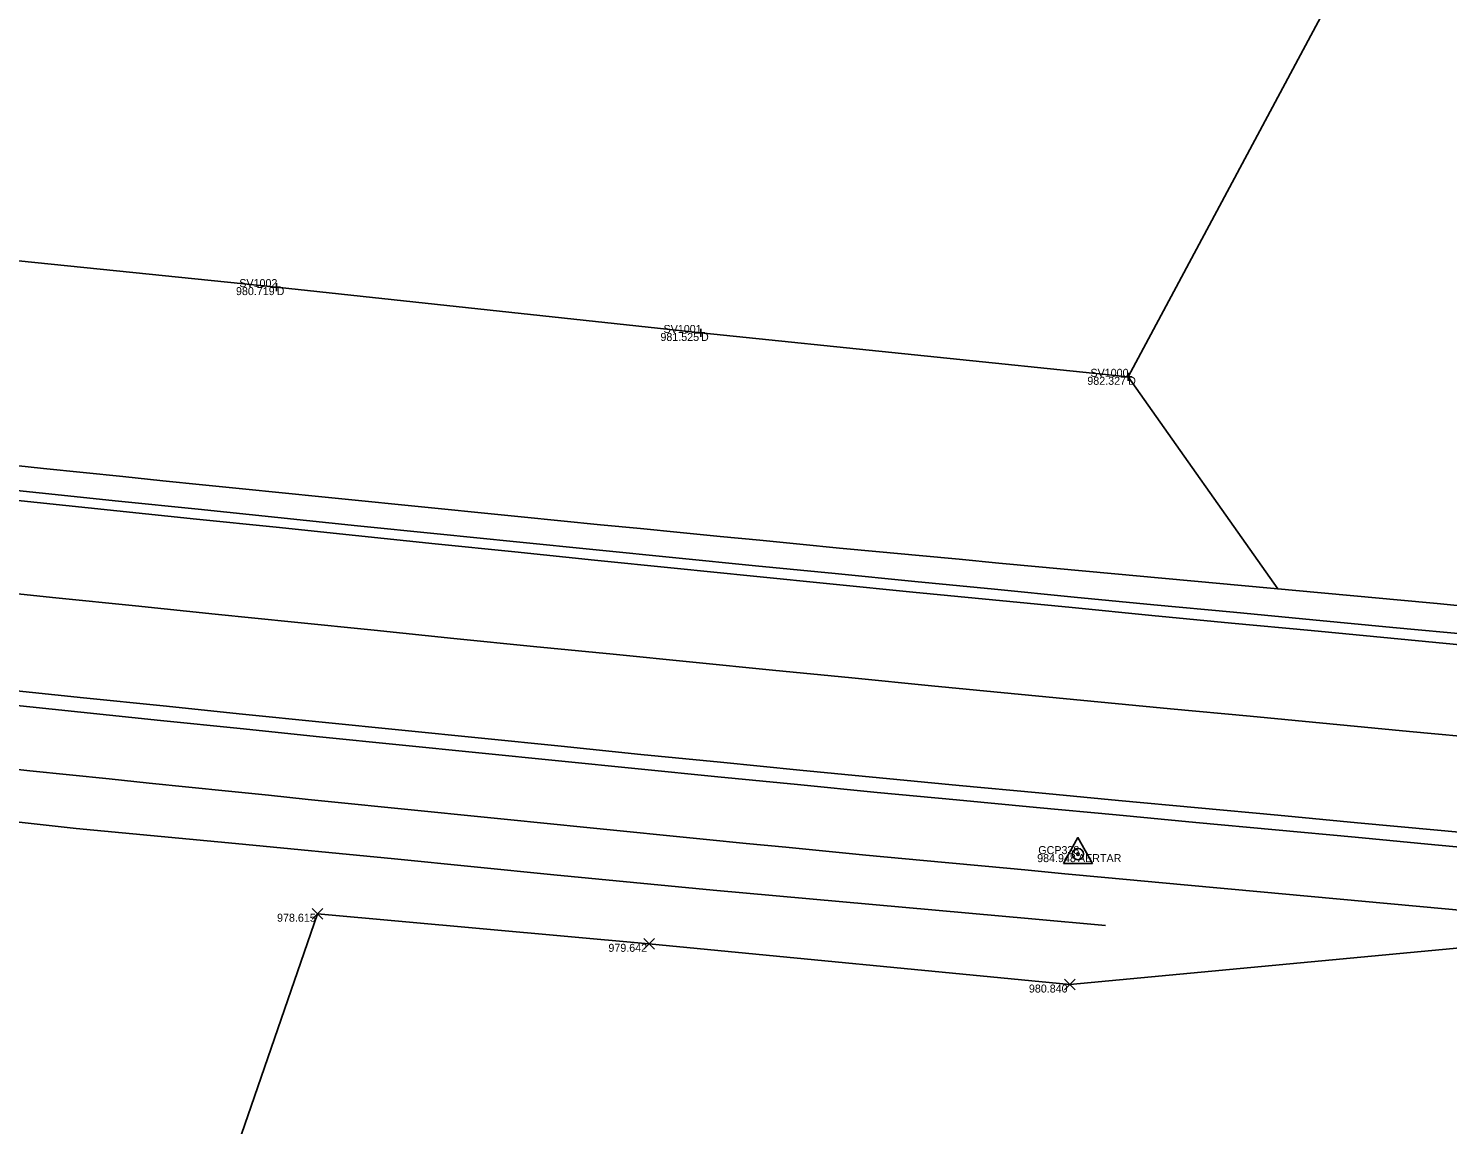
# Model space of a CAD drawing. Extents: x 2065431 to 2068157, y 709104 to 709719.
# Drawn here: x 2067334.4 to 2067511.8, y 709241.9 to 709378.9 of the extents above; entities that cross this region are included whole.
import ezdxf

# ---------------------------------------------------------------- set-up
doc = ezdxf.new("R2010")
doc.units = 0
for name, color, linetype in [('DT_X_Break_Line', 7, 'Continuous'), ('DT_X_Terrain_Boundary', 7, 'Continuous'), ('PM_X_Edge_Line', 7, 'Continuous'), ('PM_X_Lane_Line', 7, 'Continuous'), ('PV_X_EOP', 7, 'Continuous'), ('PV_X_Shoulder_Rumble_Strip', 7, 'Continuous'), ('RS_Raster1', 7, 'Continuous'), ('RW_X_CL_100_Bearings', 7, 'Continuous'), ('RW_X_Fee_WL', 7, 'Continuous'), ('SV_P_Aerial_Targets', 7, 'Continuous'), ('SV_X_Mon_Cells_Found', 7, 'Continuous'), ('SV_X_Text_Elevation', 7, 'Continuous'), ('SV_X_Text_Name', 7, 'Continuous')]:
    doc.layers.add(name, color=color, linetype=linetype)

msp = doc.modelspace()

# ---------------------------------------------------------------- linework, layer by layer
at = {"layer": 'DT_X_Break_Line'}
msp.add_lwpolyline([(2067101.73, 709304.2), (2067121.64, 709302.33), (2067141.54, 709300.39), (2067161.43, 709298.3), (2067181.3, 709296.03), (2067201.15, 709293.56), (2067221.05, 709291.6), (2067240.96, 709289.7), (2067260.87, 709287.74), (2067280.77, 709285.77), (2067300.65, 709283.57), (2067320.49, 709281.09), (2067340.37, 709278.88), (2067360.28, 709276.99), (2067380.18, 709275.07), (2067400.09, 709273.09), (2067419.99, 709271.15), (2067439.91, 709269.35), (2067459.83, 709267.56), (2067469.03, 709266.73)], dxfattribs=at)
at = {"layer": 'DT_X_Terrain_Boundary'}
for points in [[(2067515.45, 709306.5), (2067510.47, 709306.96), (2067505.49, 709307.42), (2067500.51, 709307.88), (2067495.53, 709308.34), (2067490.55, 709308.8), (2067471.85, 709335.31), (2067499.1, 709386.26), (2067504.26, 709386.13), (2067509.24, 709385.64), (2067514.22, 709385.16)], [(2067102.37, 709178.61), (2067140.67, 709165.08), (2067183.02, 709149.8), (2067239.23, 709115.87), (2067261.89, 709104.93), (2067274.06, 709104.86), (2067277.37, 709106.22), (2067284.73, 709107.64), (2067304.22, 709108.67), (2067329.31, 709129.97), (2067346.3, 709160.09), (2067342.01, 709185.45), (2067370.56, 709268.21), (2067411.97, 709264.45), (2067464.57, 709259.36), (2067538.62, 709266.34)]]:
    msp.add_lwpolyline(points, dxfattribs=at)
at = {"layer": 'PM_X_Edge_Line'}
for points in [[(2067325.57, 709320.65), (2067335.52, 709319.61), (2067345.46, 709318.57), (2067355.41, 709317.53), (2067365.36, 709316.5), (2067375.3, 709315.47), (2067385.25, 709314.45), (2067395.2, 709313.43), (2067405.15, 709312.41), (2067415.1, 709311.4), (2067425.04, 709310.4), (2067434.99, 709309.4), (2067444.95, 709308.41), (2067454.9, 709307.44), (2067464.85, 709306.47), (2067474.8, 709305.5), (2067484.76, 709304.54), (2067494.71, 709303.59), (2067504.67, 709302.64), (2067514.62, 709301.7)], [(2067331.35, 709296.24), (2067341.29, 709295.21), (2067351.24, 709294.18), (2067361.19, 709293.16), (2067371.14, 709292.14), (2067381.09, 709291.13), (2067391.04, 709290.13), (2067400.99, 709289.13), (2067410.94, 709288.13), (2067420.89, 709287.14), (2067430.84, 709286.16), (2067440.79, 709285.19), (2067450.75, 709284.25), (2067460.7, 709283.31), (2067470.66, 709282.37), (2067480.62, 709281.44), (2067490.57, 709280.51), (2067500.53, 709279.58), (2067510.49, 709278.66), (2067520.44, 709277.73)]]:
    msp.add_lwpolyline(points, dxfattribs=at)
at = {"layer": 'PM_X_Lane_Line'}
msp.add_lwpolyline([(2067327.9, 709308.73), (2067337.84, 709307.7), (2067347.79, 709306.67), (2067357.74, 709305.65), (2067367.69, 709304.64), (2067377.64, 709303.63), (2067387.59, 709302.62), (2067397.54, 709301.62), (2067407.49, 709300.63), (2067417.44, 709299.64), (2067427.39, 709298.66), (2067437.34, 709297.68), (2067447.29, 709296.71), (2067457.25, 709295.75), (2067467.2, 709294.79), (2067477.15, 709293.83), (2067487.11, 709292.88), (2067497.07, 709291.94), (2067507.02, 709291), (2067516.98, 709290.07)], dxfattribs=at)
at = {"layer": 'PV_X_EOP'}
for points in [[(2067331.31, 709324.38), (2067336.29, 709323.87), (2067341.26, 709323.35), (2067346.23, 709322.84), (2067351.21, 709322.33), (2067356.18, 709321.82), (2067361.16, 709321.32), (2067366.13, 709320.81), (2067371.1, 709320.31), (2067376.08, 709319.81), (2067381.05, 709319.31), (2067386.03, 709318.81), (2067391, 709318.31), (2067395.98, 709317.82), (2067400.96, 709317.32), (2067405.93, 709316.83), (2067410.91, 709316.34), (2067415.88, 709315.85), (2067420.86, 709315.36), (2067425.84, 709314.88), (2067430.81, 709314.4), (2067435.79, 709313.91), (2067440.77, 709313.43), (2067445.74, 709312.96), (2067450.72, 709312.5), (2067455.7, 709312.03), (2067460.68, 709311.57), (2067465.66, 709311.11), (2067470.64, 709310.64), (2067475.61, 709310.18), (2067480.59, 709309.72), (2067485.57, 709309.26), (2067490.55, 709308.8), (2067495.53, 709308.34), (2067500.51, 709307.88), (2067505.49, 709307.42), (2067510.47, 709306.96), (2067515.45, 709306.5)], [(2067329.6, 709286.6), (2067334.58, 709286.08), (2067339.55, 709285.57), (2067344.52, 709285.05), (2067349.5, 709284.54), (2067354.47, 709284.03), (2067359.44, 709283.52), (2067364.42, 709283.01), (2067369.39, 709282.5), (2067374.37, 709281.99), (2067379.34, 709281.49), (2067384.32, 709280.98), (2067389.29, 709280.48), (2067394.27, 709279.98), (2067399.24, 709279.48), (2067404.22, 709278.98), (2067409.19, 709278.49), (2067414.17, 709277.99), (2067419.14, 709277.5), (2067424.12, 709277), (2067429.09, 709276.51), (2067434.07, 709276.02), (2067439.05, 709275.54), (2067444.02, 709275.07), (2067449, 709274.61), (2067453.98, 709274.14), (2067458.96, 709273.68), (2067463.94, 709273.21), (2067468.92, 709272.75), (2067473.89, 709272.29), (2067478.87, 709271.83), (2067483.85, 709271.37), (2067488.83, 709270.9), (2067493.81, 709270.45), (2067498.79, 709269.99), (2067503.77, 709269.53), (2067508.75, 709269.07), (2067513.73, 709268.61)]]:
    msp.add_lwpolyline(points, dxfattribs=at)
at = {"layer": 'PV_X_Shoulder_Rumble_Strip'}
for points in [[(2067325.8, 709321.87), (2067335.75, 709320.82), (2067345.69, 709319.78), (2067355.64, 709318.75), (2067365.59, 709317.72), (2067375.53, 709316.7), (2067385.48, 709315.69), (2067395.43, 709314.68), (2067405.38, 709313.68), (2067415.33, 709312.68), (2067425.28, 709311.69), (2067435.23, 709310.71), (2067445.19, 709309.73), (2067455.14, 709308.76), (2067465.09, 709307.79), (2067475.05, 709306.83), (2067485, 709305.88), (2067494.95, 709304.93), (2067504.91, 709303.98), (2067514.87, 709303.05)], [(2067331.03, 709294.43), (2067340.97, 709293.4), (2067350.92, 709292.37), (2067360.87, 709291.35), (2067370.81, 709290.33), (2067380.76, 709289.32), (2067390.71, 709288.32), (2067400.66, 709287.32), (2067410.61, 709286.32), (2067420.56, 709285.33), (2067430.52, 709284.35), (2067440.47, 709283.38), (2067450.42, 709282.44), (2067460.38, 709281.5), (2067470.34, 709280.56), (2067480.29, 709279.63), (2067490.25, 709278.7), (2067500.21, 709277.77), (2067510.16, 709276.84), (2067520.12, 709275.92)]]:
    msp.add_lwpolyline(points, dxfattribs=at)
at = {"layer": 'RS_Raster1'}
for p, q in [((2067364.94, 709346.52), (2067365.94, 709346.52)), ((2067365.44, 709347.02), (2067365.44, 709346.02)), ((2067365.44, 709346.52), (2067365.44, 709346.52)), ((2067417.97, 709340.79), (2067418.97, 709340.79)), ((2067418.47, 709341.29), (2067418.47, 709340.29)), ((2067418.47, 709340.79), (2067418.47, 709340.79)), ((2067471.35, 709335.31), (2067472.35, 709335.31)), ((2067471.85, 709335.81), (2067471.85, 709334.81)), ((2067471.85, 709335.31), (2067471.85, 709335.31))]:
    msp.add_line(p, q, dxfattribs=at)
at = {"layer": 'RW_X_CL_100_Bearings'}
for p, q in [((2067369.89, 709267.54), (2067371.23, 709268.87)), ((2067369.89, 709268.87), (2067371.23, 709267.54)), ((2067411.31, 709263.79), (2067412.64, 709265.12)), ((2067411.31, 709265.12), (2067412.64, 709263.79)), ((2067463.9, 709258.7), (2067465.23, 709260.03)), ((2067463.9, 709260.03), (2067465.23, 709258.7))]:
    msp.add_line(p, q, dxfattribs=at)
at = {"layer": 'RW_X_Fee_WL'}
msp.add_lwpolyline([(2067471.85, 709335.31), (2067418.47, 709340.79), (2067365.44, 709346.52), (2067311.12, 709352.06), (2067246.93, 709356.31), (2067194.13, 709363.68), (2067159.44, 709368.67)], dxfattribs=at)
at = {"layer": 'SV_P_Aerial_Targets'}
msp.add_lwpolyline([(2067463.78, 709274.5), (2067467.38, 709274.5), (2067465.58, 709277.72)], close=True, dxfattribs=at)
for radius in [0.7, 0.16]:
    msp.add_circle((2067465.58, 709275.66), radius, dxfattribs=at)

# ---------------------------------------------------------------- texts
at = {"layer": 'SV_X_Mon_Cells_Found'}
for s, p in [('SV1002', (2067360.77, 709346.52)), ('SV1001', (2067413.79, 709340.79)), ('SV1000', (2067467.14, 709335.31)), ('GCP338', (2067460.62, 709275.66))]:
    msp.add_text(s, height=1, dxfattribs=at).set_placement(p)
at = {"layer": 'SV_X_Text_Elevation'}
for s, p in [('D', (2067365.44, 709345.52)), ('D', (2067418.47, 709339.79)), ('D', (2067471.85, 709334.31)), ('AERTAR', (2067465.58, 709274.66))]:
    msp.add_text(s, height=1, dxfattribs=at).set_placement(p)
at = {"layer": 'SV_X_Text_Name'}
for s, p in [('980.719', (2067360.36, 709345.52)), ('981.525', (2067413.4, 709339.79)), ('982.327', (2067466.75, 709334.31)), ('984.948', (2067460.48, 709274.66)), ('978.615', (2067365.49, 709267.21)), ('979.642', (2067406.9, 709263.45)), ('980.840', (2067459.45, 709258.36))]:
    msp.add_text(s, height=1, dxfattribs=at).set_placement(p)

doc.saveas('drawing.dxf')
